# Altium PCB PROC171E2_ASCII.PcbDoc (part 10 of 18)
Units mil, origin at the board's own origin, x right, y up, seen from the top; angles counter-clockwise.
Board outline 7700 x 2300 mil, 6 copper layers (Top Layer, GND 1, SIG 1, SIG 2, GND 2, Bottom Layer), stack 61.062 mil thick; 938 components, 688 nets, 11933 pads, 1723 vias.
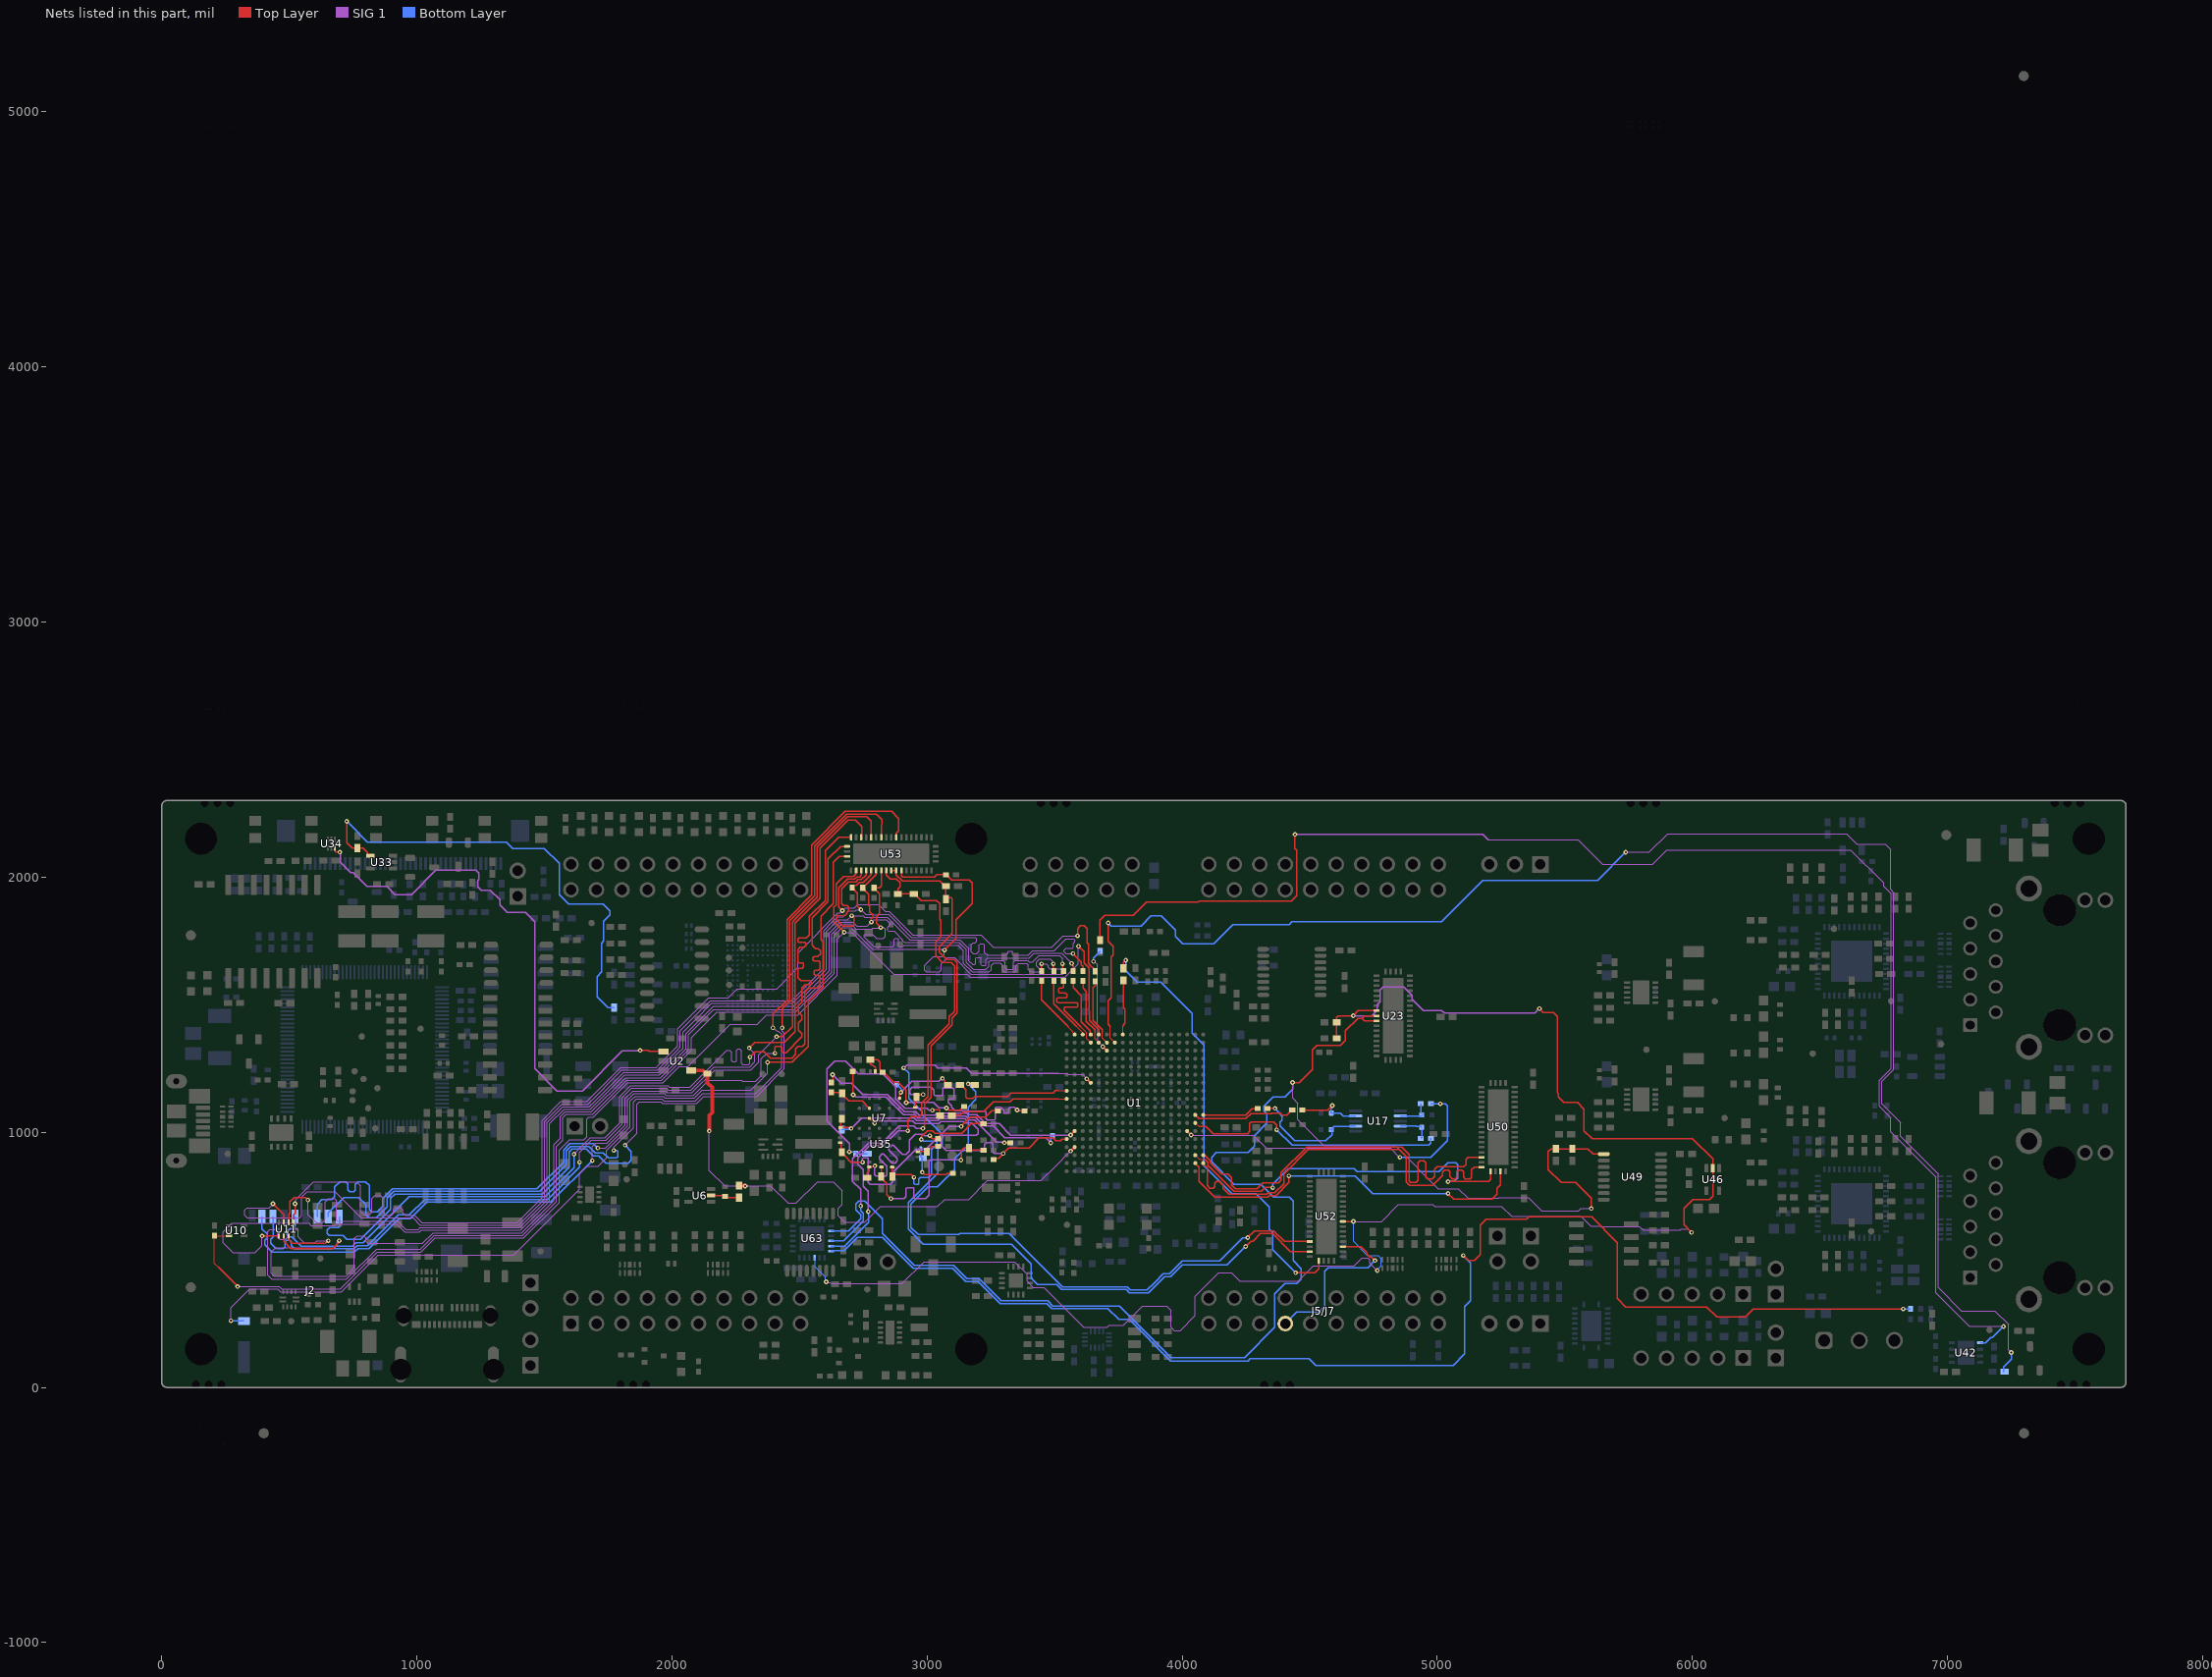
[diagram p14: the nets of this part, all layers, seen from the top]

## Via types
v1: diameter 18, hole 8, Top Layer to Bottom Layer, tented both sides, 1592 vias
v2: diameter 19.68, hole 7.87, Top Layer to Bottom Layer, tented both sides, 104 vias
v3: diameter 19.68, hole 7.87, Top Layer to Bottom Layer, 24 vias
v4: diameter 18, hole 8, Top Layer to Bottom Layer, 3 vias

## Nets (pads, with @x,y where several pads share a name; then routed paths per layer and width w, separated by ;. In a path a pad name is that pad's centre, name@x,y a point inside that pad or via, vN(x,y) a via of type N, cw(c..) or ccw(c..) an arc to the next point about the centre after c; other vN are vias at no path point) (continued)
AM263P_LIN2_TXD: R166.1 U52.39 | length 1782.1
  Top Layer w5.3: R166.1@3769.66,1642.44 3769.66,1665.2 v1(3778.82,1674.36) ; v1(4444.77,448.84) 4445.11,448.5 4519.71,448.5 4535.47,464.27 U52.39@4535.47,496.77
  Bottom Layer w5.3: v1(3778.82,1674.36) 3778.85,1661.78 3778.85,1657.39 3776.22,1654.76 3773,1651.53 3773,1638 3817.25,1593.75 3822.43,1588.57 3916.48,1588.57 3918.04,1587.02 4040,1465.06 4040,1388.66 4085.85,1342.81 4085.85,868.87 4195.74,758.98 4290,758.98 4341.87,707.11 4341.87,621.43 4354.64,608.66 4354.64,538.97 v1(4444.77,448.84)
AM263P_LIN2_TXD_PR0_PRU0_GPIO9: J5/J7.44 U52.3 | length 686.2
  Top Layer w5.3: U52.3@4629.96,551.89 4700.67,551.89 4724.05,528.5 4724.05,521.53 4735.14,510.45 4742.25,510.45 v1(4755.76,496.94)
  Bottom Layer w5.3: J5/J7.44@4404.17,250 4449.17,295 4535.31,295 4558.86,318.54 4558.86,454.51 4572.72,468.37 4727.19,468.37 v1(4755.76,496.94)
AM263P_LIN2_TXD_R: R166.2 U1.A8 | length 218.4
  Top Layer w4: U1.A8@3767.61,1382.8 3767.61,1414.29
  Top Layer w5.3: 3767.61,1414.29 3767.61,1418.04 3775.9,1426.33 3775.9,1481.99 3769.66,1488.22 R166.2@3769.66,1595.2
AM263P_MCAN3_RX: R249.1 U1.B7 | length 6218.3
  Top Layer w4: 3718.3,1414.47 3718.54,1414.23 3718.54,1369.1 U1.B7@3736.16,1351.48
  Top Layer w5.3: v1(3710,1820.18) 3710.05,1820.13 3710.05,1748.76 3729.52,1729.29 3729.52,1724.38 3729.57,1724.32 3729.57,1693.81 3721.77,1686.01 3721.77,1569.08 3721.56,1568.87 3721.56,1527.25 3710.06,1515.75 3710.06,1422.71 3718.3,1414.47
  SIG 1 w4.75: v1(5738.52,2097.5) 5831.21,2097.5 5903.56,2169.85 6604.05,2169.85 6643.91,2129.99 6756.07,2129.99 6777.03,2109.04 6777.03,1951.63 6789.52,1939.14 6789.52,1335.16 6789.52,1246.1 6743.49,1200.06 6743.49,1110.67 6815.53,1038.63 6815.53,984.47 6964.3,835.7 6964.3,390.66 7054.96,300 7185.73,300 7238.93,246.79 7238.93,147.52 v1(7250,136.46)
  Bottom Layer w5.3: v1(3710,1820.18) 3710.6,1820.18 3722.29,1808.49 3838.74,1808.49 3877.8,1847.55 3918.43,1847.55 3974.4,1791.58 3974.4,1766.76 4002.88,1738.28 4123.15,1738.28 4199.21,1814.33 4419.42,1814.33 4430.26,1825.18 5015.92,1825.18 5177.59,1986.84 5627.87,1986.84 v1(5738.52,2097.5) ; R249.1@7219.69,61.46 7219.69,79.68 7250,110 v1(7250,136.46)
AM263P_MCAN3_TX: R401.1 U42.1 | length 5733.5
  Top Layer w5.3: R401.1@3678.01,1749.69 R401.1@3679.98,1751.65 ; R401.1@3678.01,1753.62 3678.01,1830.11 3697.42,1849.52 3807.81,1849.52 3859.79,1901.5 4063.15,1901.5 4067.23,1905.58 4427.03,1905.58 4448.86,1927.4 4448.86,2105.88 4442.21,2112.53 v1(4442.21,2167.19)
  SIG 1 w4.75: 5200,2146.14 5552.02,2146.14 5647.16,2051 5844,2051 5899.97,2106.97 6620.38,2106.97 6750,1977.35 6750,1964.45 6779.47,1934.98 6779.47,1330.99 6779.47,1250.26 6733.44,1204.22 6733.44,1101.56 6777.03,1057.97 6777.03,1001.63 6954.25,824.41 6954.25,370.75 7086.18,238.82 v1(7219.69,238.82)
  SIG 1 w5.3: v1(4442.21,2167.19) 5178.95,2167.19 5200,2146.14
  Bottom Layer w5.3: U42.1@7127.91,174.84 7148.62,174.84 7169.59,195.81 7176.68,195.81 v1(7219.69,238.82)
AM263P_MCAN5_RX: U1.G4 U52.37 | length 3350.7
  Top Layer w5.3: v1(4248.9,552.05) 4249.56,552.05 4270.75,573.23 4277.33,573.23 4307.29,603.19 4353.85,603.19 4424.84,532.2 U52.37@4500.04,532.2
  Top Layer w10: v1(3625.87,1209.57) U1.G4@3641.62,1193.82
  SIG 1 w4: 3515.64,1230.74 3548.57,1230.74 3553.24,1226.06 3609.38,1226.06 v1(3625.87,1209.57)
  SIG 1 w5.3: v1(2908.1,1252.01) v1@2911.51,1252.01 ; v1@2911.51,1253.55 2920.61,1262.64 3031.75,1262.64 3042.39,1252.01 3153.29,1252.01 3174.56,1230.74 3515.64,1230.74
  Bottom Layer w5.3: v1(2908.1,1252.01) 2928.54,1231.57 2928.54,1133.26 2981.03,1080.77 2981.03,1069.89 3059.43,991.49 3059.43,950.66 3042.1,933.34 3042.1,839.53 2926.28,723.72 2926.28,636.68 2926.34,636.62 2926.34,620.07 2984.95,561.47 3330.22,561.47 3408.32,483.36 3408.32,427.64 3433.18,402.78 3507.09,402.78 3526.79,383.08 3780.43,383.08 3792.52,370.98 3867.44,370.98 3930.93,434.47 3954.71,434.47 4000.11,479.86 4174.91,479.86 4247.09,552.05 v1(4248.9,552.05)
AM263P_MCAN5_TX: R393.1 U52.35 | length 2509.6
  Top Layer w5.3: v1(3161.4,1189.84) R393.1@3187.04,1189.84 ; v1(4257.03,587.12) 4283.7,613.79 4358.24,613.79 4400.46,571.57 U52.35@4500.04,571.57
  Bottom Layer w5.3: v1(3161.4,1189.84) 3161.51,1189.84 3191.13,1160.22 3191.13,1127.96 3161.94,1098.76 3161.94,949.51 3108.72,896.29 3108.72,854.23 3041.29,786.8 3004.36,786.8 2936.88,719.32 2936.88,641.07 2936.94,641.01 2936.94,626.69 2964.58,599.05 2991.85,599.05 2992.14,598.77 3125.4,598.77 3129.26,602.64 3322.22,602.64 3531.18,393.68 3784.82,393.68 3796.91,381.58 3862.98,381.58 3893.03,411.63 3893.1,411.63 3926.54,445.07 3950.32,445.07 4001,495.75 4146.65,495.75 4237.43,586.52 4256.43,586.52 v1(4257.03,587.12)
AM263P_MCAN_STB: R248.2 U63.12 | length 5352.3
  Top Layer w5.3: v1(5101.72,516.99) 5121.65,497.06 5145.27,497.06 5168.3,520.09 5168.3,636.5 5181.69,649.89 5182.53,649.89 5191.73,659.09 5350.16,659.09 5359.07,668 5604.62,668 5705.96,566.66 5705.96,348.37 5739.06,315.27 6056.52,315.27 6096.31,275.48 6207.26,275.48 6239.03,307.24 v1(6826.84,307.24)
  Bottom Layer w5.3: U63.12@2623.77,534.26 2624.48,534.97 2639.07,534.97 2639.16,535.06 2674.13,535.06 2727.29,588.23 2824.14,588.23 2945.89,466.48 3100.81,466.48 3152.4,414.89 3199.9,414.89 3286.21,328.58 3468.82,328.58 3488.75,308.65 3708.84,308.65 3751.67,265.83 3792.01,265.83 3954.71,103.13 4257.79,103.13 4266.49,111.82 4497.18,111.82 4523.75,85.25 5060.87,85.25 5061.63,86.01 5062.07,86.01 5106.93,130.86 5106.93,313.17 5107.42,313.67 5107.42,316.96 5130.3,339.84 5130.3,488.41 v1(5101.72,516.99) ; v1@6826.26,307.24 v1(6826.84,307.24) R248.2@6855,307.24
AM263P_MDIO0_MDC: R61.1 R63.1 U17.9 | length 126.5
  Bottom Layer w5.3: U17.9@4855.28,1024.06 4856.52,1025.31 4916.69,1025.31 4919.5,1022.5 4935.6,1022.5 R63.1@4939.04,1019.06 ; R61.1@4935.59,975.79 4940,980.2 R63.1@4940,1013.63
AM263P_MDIO0_MDC_R: R61.2 U1.M17 | length 1050.8
  Top Layer w4: U1.M17@4051.07,1036.34 4065.59,1021.81
  Top Layer w5.3: 4065.59,1021.81 4093.28,1021.81 4114.06,1001.03 4121.4,993.69 4255.66,993.69 4265.03,1003.07 4265.03,1035.03 4270.92,1040.92 4357.99,1040.92 4370.7,1028.21 v1(4370.7,1009.53)
  Bottom Layer w5.3: v1(4370.7,1009.53) 4431.44,948.79 4966.19,948.79 4975,957.6 4975,975.75 R61.2@4974.96,975.79
AM263P_MDIO0_MDIO: R62.1 R64.1 U17.7 | length 132.8
  Bottom Layer w5.3: U17.7@4855.28,1063.43 R64.1@4941.22,1063.43 ; R62.1@4935.59,1111.7 4935.59,1075.62 4941.21,1070 R64.1@4944,1070
AM263P_MDIO0_MDIO_R: R62.2 U1.N16 | length 1294.4
  Top Layer w10: U1.N16@4019.57,1004.84 v1(4035.32,989.09)
  SIG 1 w4: v1(4035.32,989.09) 4114.06,989.09
  SIG 1 w4.75: 4114.06,989.09 4278.7,989.09 4330.25,937.54 4815.65,937.54 4851.26,901.93 v1(4853.62,901.93)
  Bottom Layer w5.3: v1(4853.62,901.93) 4974.46,901.93 5040,967.46 5040,1103 5031.39,1111.61 v1(5011.92,1111.61) 5011.82,1111.7 R62.2@4974.96,1111.7
AM263P_MMC0_CD: R40.1 U1.A5 U10.3 U53.2 | length 5276.1
  Top Layer w4.75: 222.39,469.98 206.73,485.63 R40.1@206.73,594.53 U10.3@263.65,594.53
  Top Layer w5.3: 222.39,469.98 v1(297.36,395) ; v1(2675.17,1783.7) 2675.17,1785.34 2635.14,1825.37 2635.14,1882.38 2643.93,1891.16 2643.93,1972.58 2673.77,2002.43 2711.32,2002.43 2720.37,2011.48 2720.37,2024.45 U53.2@2721.99,2026.07 ; v1(3593.34,1728.9) 3615,1707.24 3615,1664.03 3630.89,1648.14 3630.89,1648.08 3635.54,1643.43 3635.54,1515.34 3635.55,1515.28 3636.55,1438.26 3673.12,1401.69 U1.A5@3673.12,1382.8
  SIG 1 w4.75: v1(297.36,395) 298.07,395.71 366.87,395.71 458.05,395.71 458.6,395.16 459.06,395.16 469.24,384.98 699.94,384.98 844.54,529.57 1015.53,529.57 1071.84,585.89 1418.95,585.89 1557.84,724.79 1557.84,929.75 1599.1,971 1654.47,971 1666.71,983.24 1666.71,1051.71 1674,1059 1692,1059 1826.76,1193.76 1964.09,1193.76 1990.85,1220.53 2027.73,1257.4 2062.18,1257.4 2228.28,1423.5 2334.78,1423.5 2371.71,1460.43 2494.1,1460.43 2648.8,1615.13 2648.8,1757.33 v1(2675.17,1783.7) 2704.67,1783.7 2868.35,1620.03 2869.74,1618.63 3158.35,1618.63 3169.18,1607.81 3540.26,1607.81 3592.78,1660.33 3592.78,1693.97 3593.34,1694.52 v1(3593.34,1728.9)
AM263P_MMC0_CD_MUX: J2.9 U53.41 | length 3773.6
  Top Layer w5.3: v1(2374.56,1274.02) 2470.81,1274.02 2533.98,1337.18 2533.98,1376.45 2533.98,1511.43 2592.56,1570.01 2592.56,1747.03 2583.63,1755.96 2583.63,1833.15 2583.63,1845.86 2633.33,1895.55 2633.33,2058.59 2655.93,2081.19 U53.41@2686.56,2081.19
  SIG 1 w4.75: v1(271.44,261.02) 271.44,312.62 344.21,385.39 453.96,385.39 454.23,385.11 454.89,385.11 465.35,374.65 704.22,374.65 848.81,519.25 942.15,519.25 942.21,519.19 1379.33,519.19 1637.5,777.36 1637.5,837.94 1665.63,866.06 1709.86,866.06 1743.85,900.05 1743.85,928.21 1836.74,1021.11 1836.74,1122.46 1855.31,1141.04 1965.77,1141.04 1972.5,1134.31 2087.91,1134.31 2118.97,1165.38 2309.98,1165.38 2374.56,1229.95 v1(2374.56,1274.02)
  Bottom Layer w5.3: v1(271.44,261.02) 272.3,260.16 J2.9@321.97,260.16
AM263P_MMC0_CLK: R33.2 U11.1 U53.3 | length 4813.5
  Top Layer w5.3: U11.1@517.72,646.57 517.72,676.24 522.76,681.27 v1(522.76,719.45) ; v1(2668.36,1868.31) 2654.53,1882.15 2654.53,1957.78 2688.57,1991.83 2715.71,1991.83 2725.05,2001.17 2735.53,2001.17 2741.68,2007.32 U53.3@2741.68,2026.07 ; v1(3590,1770) 3590,1799.21 3600.13,1809.34 3615.78,1809.34 3627.54,1797.58 3627.54,1742.08 3632.71,1736.91 3632.71,1661.32 3641.49,1652.53 3652.35,1641.68 3652.35,1638.24 R33.2@3659.54,1631.05
  SIG 1 w4.75: v1(522.76,719.45) 524.7,721.39 524.7,735.57 595.21,806.09 764.45,806.09 780,790.54 780,689.1 791.64,677.46 815.94,677.46 823.99,685.51 823.99,739.81 835.39,751.21 858.79,751.21 871.44,738.56 871.44,680.97 878.15,674.26 900,674.26 907.66,681.93 907.66,698.12 915,705.46 935.75,705.46 945,696.21 945,684.26 955,674.26 991.71,674.26 1019.78,646.19 1393.97,646.19 1490.63,742.85 1490.63,1046.3 1564.66,1120.32 1665.63,1120.32 1799.37,1254.06 1939.11,1254.06 1941.89,1256.84 cw(c2276.21,957.37) 1961.39,1277.28 1995.86,1311.2 2022.85,1338.19 2022.85,1406.06 2142.92,1526.14 2219.72,1526.14 2256.12,1562.54 2410.68,1562.54 2494.16,1646.02 2494.16,1701.51 2570.79,1778.14 2572.18,1779.53 2572.18,1782.04 2649.82,1859.67 2659.9,1859.67 2668.36,1868.13 v1(2668.36,1868.31) ; v1@2668.45,1868.22 2678.73,1878.5 2715.55,1878.5 2728.65,1891.6 2808.88,1891.6 2810.79,1889.69 2835.79,1864.7 2851.85,1864.7 2941.55,1775 2942.94,1773.61 3211.39,1773.61 3260.01,1724.99 3488.2,1724.99 3533.21,1770 v1(3590,1770)
AM263P_MMC0_CLK_MUX: J2.5 U53.39 | length 3759.8
  Top Layer w5.3: v1(2305.75,1294.59) 2326.61,1315.45 2360.73,1315.45 2385.77,1290.42 2470.46,1290.42 2485.1,1305.05 2485.1,1326.89 2494.5,1336.29 2510.53,1336.29 2520.65,1346.41 2520.65,1550.44 2535.68,1565.47 2573.03,1565.47 2581.43,1573.87 2581.43,1609.25 2574.89,1615.78 2560.89,1615.78 2557.78,1618.89 2557.78,1632.28 2560.89,1635.38 2575.45,1635.38 2581.43,1641.35 2581.43,1665.96 2576.68,1670.71 2558.11,1670.71 2552.12,1676.7 2552.12,1682.82 2557.99,1688.69 2571.83,1688.69 2581.96,1698.82 2581.96,1711.43 2573.23,1720.16 2563.14,1720.16 2551.7,1731.59 2551.7,1732.67 2549.32,1735.06 2549.32,1833.15 2549.32,1841.52 2612.13,1904.34 2612.13,2071.87 2660.82,2120.56 U53.39@2686.56,2120.56
  SIG 1 w4.75: v1(1615.98,914.12) 1615.98,914.45 1679.34,977.81 1680.12,977.81 1680.33,978.02 1736.73,978.02 1795,1036.29 1795,1140.68 1837.75,1183.44 1983.34,1183.44 1990.06,1176.71 2070.35,1176.71 2214.27,1320.63 2227.09,1320.63 2234.25,1313.48 2234.25,1280.57 2238.3,1276.53 2248.73,1276.53 2252.53,1280.32 2252.53,1320.14 2258.78,1326.4 2265.47,1326.4 2271.96,1319.91 2271.96,1270.43 2276.34,1266.06 2300.9,1266.06 2305.75,1270.91 v1(2305.75,1294.59)
  Bottom Layer w5.3: J2.5@522.76,669.61 522.76,634.79 509.41,621.44 502.92,621.44 491.43,609.95 491.43,599.14 501.08,589.49 510.38,589.49 546.06,553.81 748.96,553.81 760.91,565.76 788.8,565.76 970.06,747.02 1502.58,747.02 1615.98,860.43 v1(1615.98,914.12)
AM263P_MMC0_CLK_R: R33.1 U1.B6 | length 266.1
  Top Layer w4: 3687.64,1387.89 3687.64,1368.27 U1.B6@3704.61,1351.3
  Top Layer w5.3: R33.1@3659.54,1591.68 3659.54,1575.93 3650.97,1567.36 3650.97,1438.83 3687.64,1402.16 3687.64,1387.89
AM263P_MMC0_CMD: R34.2 U11.2 U53.4 | length 4889.6
  Top Layer w5.3: U11.2@498.04,646.57 498.04,678.5 503.23,683.69 503.23,727.54 519.46,743.77 563.58,743.77 v1(573.09,734.25) ; v1(2704.82,1848.92) 2713.5,1840.23 2713.5,1810.27 2710.4,1807.17 2670.78,1807.17 2645.74,1832.21 2645.74,1846.82 2648.1,1849.18 2648.84,1849.92 2653.24,1849.92 2666.79,1848.77 ccw(c2668.45,1868.22) 2684.52,1857.13 2692.59,1868.82 2692.59,1882.16 2685.54,1889.22 2672.73,1889.22 2665.13,1896.82 2665.13,1953.39 2692.96,1981.23 2720.1,1981.23 2729.44,1990.57 2743.02,1990.57 2761.36,2008.91 U53.4@2761.36,2026.07 ; v1(3566.83,1661.6) 3566.83,1658.16 3573,1651.99 R34.2@3573,1632.17
  SIG 1 w4.75: v1(573.09,734.25) 573.09,677.22 605.31,645 628.72,645 640,656.28 640,727.32 652.68,740 676.6,740 685,731.6 685,655 689.31,650.69 925.2,650.69 957.03,618.86 1005.9,618.86 1013.13,626.09 1055.19,626.09 1402.3,626.09 1510.73,734.53 1510.73,1037.97 1572.98,1100.22 1676.37,1100.22 1810.11,1233.96 1947.43,1233.96 1959.49,1246.02 2029.06,1315.59 2042.95,1329.48 2042.95,1392.59 2093.4,1443.05 2155.67,1505.31 2473.31,1505.31 2606,1638 2606,1787.43 2626.92,1808.35 2651.87,1833.3 2689.19,1833.3 v1(2704.82,1848.92) 2749.92,1848.92 2754.33,1844.51 2755.72,1843.12 2782.57,1843.12 2782.64,1843.05 2845.07,1843.05 2846.98,1841.15 2933.23,1754.9 2934.62,1753.51 3129.7,1753.51 3163.48,1719.74 3163.48,1671.72 3178.14,1657.05 3186.14,1657.05 3191.15,1662.07 3191.15,1682.48 3193.93,1685.26 3209.52,1685.26 3212.3,1682.48 3212.3,1656.28 3215.08,1653.5 3228.41,1653.5 3231.19,1656.28 3231.19,1677.22 3237.62,1683.64 3400.47,1683.64 3418.77,1701.95 3526.48,1701.95 v1(3566.83,1661.6)
AM263P_MMC0_CMD_MUX: J2.3 U53.38 | length 3757.6
  Top Layer w5.3: v1(2403.69,1309.94) 2403.69,1333.19 2406.8,1336.29 2426.66,1336.29 2429.76,1333.19 2429.76,1317.74 2435.64,1311.86 2446.9,1311.86 2510.05,1375.01 2510.05,1385.95 2496.52,1399.48 2496.52,1429.36 2510.05,1442.89 2510.05,1458.33 2496.52,1471.86 2496.52,1497.11 2509.57,1510.17 2509.57,1564.57 2522.98,1577.98 2542.9,1577.98 2546,1581.08 2546,1591.98 2542.83,1595.14 2504.59,1595.14 2493.16,1606.58 2493.16,1638.81 2496.86,1642.52 2510.66,1642.52 2515.43,1647.29 2515.43,1660.98 2512.63,1663.77 2496.94,1663.77 2493.16,1667.56 2493.16,1716.21 2501.29,1724.35 2517.73,1724.35 2523.98,1730.6 2523.98,1740.19 2520.64,1743.53 2497.9,1743.53 2493.16,1748.27 2493.16,1758.05 2497.77,1762.66 2527.28,1762.66 2538.72,1774.1 2538.72,1833.15 2538.72,1845.91 2601.53,1908.73 2601.53,2103.35 2654.17,2156 U53.38@2702.31,2156
  SIG 1 w4.75: v1(1709.17,938.04) 1739.4,938.04 1826.05,1024.7 1826.05,1025.41 1826.14,1025.5 1826.14,1126.85 1850.92,1151.64 1970.16,1151.64 1976.89,1144.91 2083.52,1144.91 2143.03,1204.42 2273.09,1204.42 2277.03,1200.48 2329.29,1200.48 2349.67,1220.86 2349.67,1287.4 2372.22,1309.94 v1(2403.69,1309.94)
  Bottom Layer w5.3: J2.3@609.37,669.61 609.37,717.57 628,736.2 666.72,736.2 677.39,746.87 677.39,785.59 697.9,806.09 720.7,806.09 728.57,798.22 728.57,773.79 736.24,766.13 751.5,766.13 758.91,773.54 758.91,796.04 768.97,806.09 799.28,806.09 813.89,791.48 813.89,697.22 822.5,688.61 845.2,688.61 865.47,708.88 865.47,739.37 904.92,778.82 1470.84,778.82 1575.26,883.24 1575.26,930.99 1599.11,954.84 1646.86,954.84 1692.37,954.84 v1(1709.17,938.04)
AM263P_MMC0_CMD_R: R34.1 U1.A4 | length 238.4
  Top Layer w5.3: R34.1@3573,1592.8 3573,1567.42 3605,1535.42 3605,1433.11 3639.62,1398.48 3639.62,1384.79 U1.A4@3641.62,1382.8
AM263P_MMC0_D0: R35.2 R386.1 U11.3 U53.5 | length 5111.3
  Top Layer w5.3: v1(436.14,719.45) 478.35,677.24 U11.3@478.35,646.57 ; v1(2740.42,1872.35) 2740.42,1872.63 2726.86,1886.19 2726.86,1937.51 2706.97,1957.4 2706.97,1961.33 2714.16,1968.53 2722.61,1968.53 2734.05,1979.97 2750.52,1979.97 2781.05,2010.5 U53.5@2781.05,2026.07 ; v1(3571.76,1700) 3604.4,1667.36 3604.4,1659.64 ; 3604.43,1659.62 3604.43,1656.55 3611,1649.98 R35.2@3611,1632.17
  SIG 1 w4.75: v1(436.14,719.45) 420.83,704.14 334.14,704.14 325,695 325,675 335,665 539.81,665 549.08,674.26 549.08,745.74 569.32,765.98 680,765.98 781.77,664.21 984.38,664.21 1012.44,636.14 1398.14,636.14 1500.68,738.69 1500.68,1042.13 1568.82,1110.27 1669.79,1110.27 1803.53,1244.01 1943.27,1244.01 1951.6,1252.34 2017.91,1318.76 2032.9,1333.75 2032.9,1396.23 2032.9,1398.2 2035.68,1400.98 2088.46,1453.1 2151.51,1515.36 2468.36,1515.36 2595,1642 2595,1790.64 2626.92,1822.56 2647.71,1843.35 2651.41,1844.04 2671.32,1844.04 2683.53,1856.25 2691,1865.66 2693.78,1868.45 2719.71,1868.45 2723.62,1872.35 v1(2740.42,1872.35) ; v1@2740.56,1872.49 2759.88,1853.17 2786.73,1853.17 2786.8,1853.1 2806.41,1853.1 2806.56,1853.26 2849.08,1853.26 2937.39,1764.95 2938.78,1763.56 3188.99,1763.56 3193.88,1758.67 3193.88,1748 3188.96,1743.08 3180.09,1743.08 3173.53,1736.52 3173.53,1708.22 3181.71,1700.04 3194.5,1700.04 3204.48,1710.02 3204.48,1734.45 3209.44,1739.41 3222.09,1739.41 3225.68,1735.81 3225.68,1704.29 3236.28,1693.69 3308.07,1693.69 3316.97,1702.59 3316.97,1707.55 3319.75,1710.34 3332.9,1710.34 3335.68,1707.55 3335.68,1696.48 3338.46,1693.69 3396.31,1693.69 3414.61,1712 3497.75,1712 3544.42,1758.67 3574.11,1758.67 3579.33,1753.45 3579.33,1745.49 3574.09,1740.25 3574.09,1724.22 3571.3,1721.44 3544.9,1721.44 3537.18,1713.71 3537.18,1707 3544.18,1700 v1(3571.76,1700)
AM263P_MMC0_D0_MUX: J2.7 U53.36 | length 3757.7
  Top Layer w5.3: v1(2302.92,1330.48) 2324.88,1352.44 2440.17,1352.44 2464.18,1376.45 2482.56,1394.83 2482.56,1819.74 2495.97,1833.15 2580.33,1917.51 2580.33,2113.16 2690.78,2223.61 2718.42,2223.61 2744,2198.03 U53.36@2744,2156
  SIG 1 w4.75: v1(1638.2,882.48) 1638.2,921.68 1684.49,967.97 1740.9,967.97 1805.05,1032.12 1805.05,1135.74 1842.14,1172.84 1978.95,1172.84 1985.67,1166.11 2074.74,1166.11 2164.08,1255.46 2304.51,1255.46 2325.28,1276.22 2325.28,1307.19 2302.92,1329.55 v1(2302.92,1330.48)
  Bottom Layer w5.3: J2.7@436.14,669.61 436.14,589.22 427.31,580.39 427.31,564.71 448.8,543.21 475.59,543.21 482.69,550.32 482.69,569.23 489.55,576.09 501.35,576.09 507.69,569.75 507.69,555.14 519.62,543.21 753.35,543.21 765.3,555.16 806.7,555.16 927.5,675.96 970.21,675.96 1030.67,736.42 1512.41,736.42 1638.2,862.21 v1(1638.2,882.48)
AM263P_MMC0_D0_R: R35.1 U1.B5 | length 267.2
  Top Layer w4: 3657.37,1390.67 3657.37,1367.05 U1.B5@3673.12,1351.3
  Top Layer w5.3: R35.1@3611,1592.8 3611,1566 3624.4,1552.6 3624.4,1435.42 3657.37,1402.45 3657.37,1390.67
AM263P_MMC0_D1: R36.2 R385.1 U11.6 U53.6 | length 5006.3
  Top Layer w5.3: v1(393.42,593.25) 393.59,593.43 U11.6@458.67,593.43 ; v1(2781.35,1823.85) 2781.35,1836.36 2787.97,1842.98 2787.97,1851.54 2775.25,1864.27 2775.25,1887.05 2771.05,1891.25 2771.05,1933.14 2748.06,1956.14 2748.06,1960.07 2755.25,1967.27 2757.22,1967.27 2800.73,2010.78 U53.6@2800.73,2026.07 ; v1(3530.86,1660.05) 3530.86,1636.3 R36.2@3535,1632.17
  SIG 1 w4.75: v1(393.42,593.25) 393.42,554.93 366.39,527.91 278.68,527.91 240,566.59 240,610 274.25,644.25 576.46,644.25 585.85,634.85 587.24,633.46 676.72,633.46 683.9,640.64 921.04,640.64 952.86,608.81 1010.06,608.81 1017.29,616.04 1059.36,616.04 1406.46,616.04 1520.78,730.36 1520.78,1033.81 1577.14,1090.17 1680.53,1090.17 1814.27,1223.91 1951.6,1223.91 1967.2,1239.52 2033.22,1305.54 2055.08,1327.39 2055.08,1386.7 2163.18,1494.81 2478.81,1494.81 2617,1633 2617,1781.18 2658.87,1823.05 2661.16,1823.05 2661.36,1823.25 2709.1,1823.25 2725.09,1807.26 2764.76,1807.26 v1(2781.35,1823.85) 2790.51,1833 2840.91,1833 2856.22,1817.69 2856.22,1813.76 2846.37,1803.91 2846.37,1790.5 2849.15,1787.72 2870.73,1787.72 2904.17,1754.27 2904.17,1750.06 2910.77,1743.46 3125.54,1743.46 3153.43,1715.57 3153.43,1666.19 3180.41,1639.21 3229.93,1639.21 3241.53,1650.81 3241.53,1667.52 3247.6,1673.59 3298.34,1673.59 3305.82,1666.12 3305.82,1644.5 3311.58,1638.74 3335.38,1638.74 3338.72,1642.07 3338.72,1666.7 3344.57,1672.56 3395.28,1672.56 3401.22,1666.61 3413.95,1666.61 3439.23,1691.9 3519.54,1691.9 3530.86,1680.58 v1(3530.86,1660.05)
AM263P_MMC0_D1_MUX: J2.8 U53.34 | length 3758.5
  Top Layer w5.3: v1(2410.24,1374.64) 2432.79,1374.64 2471.96,1413.81 2471.96,1824.13 2480.98,1833.15 2569.73,1921.9 2569.73,2117.55 2688.33,2236.15 2764.22,2236.15 2781.05,2219.32 U53.34@2781.05,2156
  SIG 1 w4.75: v1(1688.2,888.4) 1688.2,944.69 1701.41,957.9 1743.55,957.9 1745.06,957.92 1816,1028.86 1816,1131.7 1846.53,1162.24 1974.55,1162.24 1981.28,1155.51 2079.13,1155.51 2168.47,1244.86 2308.91,1244.86 2339.07,1275.02 2339.07,1303.48 v1(2410.24,1374.64)
  Bottom Layer w5.3: J2.8@392.83,669.61 392.83,621.44 412.94,601.34 412.94,585.16 405.02,577.25 405.02,558.26 433.52,529.76 755.15,529.76 758.26,532.87 758.26,533.13 769.69,544.56 812.22,544.56 928.51,660.86 973.54,660.86 1038.51,725.82 1524.13,725.82 1686.7,888.4 v1(1688.2,888.4)
AM263P_MMC0_D1_R: R36.1 U1.B4 | length 490
  Top Layer w4: 3601.58,1414.29 3625.87,1390 3625.87,1367.05 U1.B4@3641.62,1351.3
  Top Layer w5.3: R36.1@3535,1592.8 3535.16,1592.64 3535.16,1580.99 3535.12,1580.94 3535.12,1568.69 3532.01,1565.58 3517.93,1565.58 3514.83,1562.48 3514.83,1549.97 3517.93,1546.87 3540.93,1546.87 3547.57,1540.23 3547.57,1530.56 3544.46,1527.46 3511.96,1527.46 3508.85,1524.35 3508.85,1512.26 3513.35,1507.77 3587.55,1507.77 3590.65,1504.66 3590.65,1494.1 3586.1,1489.55 3541.65,1489.55 3536.18,1484.08 3536.18,1479.69 3552.93,1462.95 3601.58,1414.29
AM263P_MMC0_D2: R37.2 R384.1 U11.7 U53.7 | length 5525.9
  Top Layer w5.3: U11.7@478.35,593.43 478.35,571.65 505.48,544.52 669.3,544.52 695.98,571.21 v1(695.98,574.65) ; R384.1@2792.16,1958.1 2812.53,1958.1 2820.42,1966 U53.7@2820.42,2026.07 ; R384.1@2792.16,1960.07 2792.16,1956.14 2813.04,1935.25 2813.04,1918.25 2814.17,1917.12 2814.17,1874.86 2814.3,1874.73 2814.3,1864.27 2814.22,1864.19 2814.22,1858.31 2800.88,1844.96 2800.88,1819.59 v1(2818.2,1802.27) ; v1(3494.86,1660.24) 3494.86,1634.3 R37.2@3497,1632.17
  SIG 1 w4.75: v1(695.98,574.65) 687.35,566.01 687.35,557.12 676.74,546.51 446.51,546.51 430.11,530.11 430.11,447.99 441.64,436.46 723,436.46 755,468.46 755,583.25 765,593.25 791.75,593.25 800,585 800,572.73 808.85,563.88 1021.4,563.88 1063.52,605.99 1410.63,605.99 1537.74,733.11 1537.74,951.54 1561.89,975.68 1561.89,1060.7 1581.31,1080.12 1684.69,1080.12 1818.44,1213.86 1955.76,1213.86 2037.37,1295.47 ; 2037.39,1295.49 2065.13,1323.23 2065.13,1382.54 2163.11,1480.53 2479.94,1480.53 2626.92,1627.52 2626.92,1628.71 2627.05,1628.84 2627.05,1777.01 2663.03,1813 2705.14,1813 2720.93,1797.21 2783.76,1797.21 2786.33,1799.78 2815.71,1799.78 v1(2818.2,1802.27) 2829.92,1802.27 2836.32,1795.87 2836.32,1768.02 2828.2,1759.9 2802.74,1759.9 2786.85,1775.79 2755.75,1775.79 2752.97,1773 2752.97,1765.17 2791.39,1726.74 2864.95,1726.74 2871.68,1733.47 2871.68,1755.76 2875.82,1759.9 2884.34,1759.9 2888.8,1755.44 2888.8,1729.53 2891.58,1726.74 2904.55,1726.74 2911.21,1733.41 3121.38,1733.41 3143.38,1711.41 3143.38,1662.03 3176.25,1629.16 3243.42,1629.16 3251.58,1637.32 3251.58,1653.74 3261.38,1663.54 3287.1,1663.54 3295.77,1654.88 3295.77,1634.13 3301.21,1628.69 3342.08,1628.69 3348.77,1635.38 3348.77,1654.22 3357.06,1662.51 3391.11,1662.51 3397.12,1656.5 3397.12,1637.97 3406.4,1628.69 3443.82,1628.69 3446.6,1631.47 3446.6,1635.4 3429.75,1652.26 3429.75,1668.2 3441.03,1679.48 3483.07,1679.48 3492.33,1670.22 3492.33,1662.78 v1(3494.86,1660.24)
AM263P_MMC0_D2_MUX: J2.1 U53.32 | length 3757
  Top Layer w5.3: v1(2431.8,1409.49) 2431.8,1484.2 2461.36,1513.76 2461.36,1828.52 2465.98,1833.15 2559.13,1926.29 2559.13,2121.94 2683.94,2246.75 2801.9,2246.75 2823.78,2224.87 2823.78,2206.08 2820.42,2202.72 U53.32@2820.42,2156
  SIG 1 w4.75: v1(1816.37,949.19) 1862.83,995.64 1862.83,1110.01 1872.66,1119.84 1956.99,1119.84 1963.72,1113.11 2096.69,1113.11 2124.66,1141.08 2332.34,1141.08 2440.36,1249.1 2440.36,1387.98 2431.8,1396.55 v1(2431.8,1409.49)
  Bottom Layer w5.3: J2.1@695.98,669.61 695.98,629.46 692.88,626.36 657.54,626.36 648.36,617.19 648.36,604.08 656.39,596.06 709.19,596.06 725.21,580.04 779.9,580.04 897.49,697.63 897.49,741.41 913.7,757.62 1491.33,757.62 1596.46,862.75 1596.46,922.21 1607.89,933.64 1665.49,933.64 1691.21,907.92 1712.5,907.92 1741.9,878.52 1828.28,878.52 1840.53,890.77 1840.53,925.02 v1(1816.37,949.19)
AM263P_MMC0_D2_R: R37.1 U1.A3 | length 257.6
  Top Layer w4: 3584.29,1415.65 3610.12,1389.82 U1.A3@3610.13,1382.8
  Top Layer w5.3: R37.1@3497,1592.8 3496.11,1591.91 3496.11,1572.59 3496.07,1572.55 3496.07,1503.87 3584.29,1415.65
AM263P_MMC0_D3: R38.2 R383.1 U11.8 U53.11 | length 5767.7
  Top Layer w5.3: U11.8@498.04,593.43 498.04,577.3 509.79,565.55 640.14,565.55 649.24,574.65 v1(652.68,574.65) ; U53.11@2899.16,2026.07 2899.16,2004.24 2903.17,2000.23 3028.68,2000.23 3037.72,2009.27 3076.02,2009.27 3095.92,1989.38 3165.37,1989.38 3177.32,1977.42 3177.32,1897.18 3113.15,1833.01 3113.15,1759.04 v1(3068.27,1714.16) ; R38.2@3449,1632.17 v1(3449,1660.23)
  SIG 1 w4.75: v1(652.68,574.65) 651.96,573.93 607.59,573.93 599.42,565.76 558.64,565.76 535,589.4 535,614.59 524.59,625 504.26,625 495.34,616.08 495.34,589.74 485,579.4 463.85,579.4 455,588.25 455,608.19 444.33,618.86 423.61,618.86 415.82,611.07 415.82,439.18 431.52,423.48 724.23,423.48 842.26,541.51 1013.25,541.51 1067.68,595.94 1414.79,595.94 1547.79,728.95 1547.79,944.32 1571.94,968.46 1571.94,1056.54 1585.47,1070.07 1688.86,1070.07 1822.6,1203.81 1959.92,1203.81 2077.07,1320.96 2077.07,1370.6 2176.96,1470.48 2484.1,1470.48 2626.92,1613.3 2637,1623.38 2637,1624.57 2637.1,1624.67 2637.1,1772.85 2667.2,1802.95 2700.98,1802.95 2787.23,1716.69 3065.74,1716.69 v1(3068.27,1714.16) 3068.27,1696.45 3059.46,1687.63 3024.43,1687.63 2990.9,1654.1 2990.9,1635.38 2997.59,1628.68 3047.94,1628.68 3056.58,1637.32 3056.58,1660.34 3080.45,1684.22 3106.98,1684.22 3171.17,1620.03 3172.56,1618.64 3373.49,1618.64 ccw(c3377.87,1637.38) 3382.25,1618.64 3530.25,1618.64 3533.03,1621.42 3533.03,1637.2 3530.25,1639.99 3481.5,1639.99 3475.46,1646.02 3475.46,1652.8 3468.03,1660.23 v1(3449,1660.23)
AM263P_MMC0_D3_MUX: J2.2 U53.29 | length 3758.9
  Top Layer w5.3: v1@2395.8,1409.72 2395.8,1463.19 2450.76,1518.15 2450.76,1832.91 2450.99,1833.15 2548.53,1930.68 2548.53,2126.33 2679.55,2257.35 2861.18,2257.35 2888.64,2229.89 2888.64,2181.62 2879.47,2172.45 U53.29@2879.47,2156
  SIG 1 w4.75: v1(1772.09,928.85) 1773.12,929.88 1773.12,941.12 1848.96,1016.96 1848.96,1118.34 1861.05,1130.44 1961.38,1130.44 1968.11,1123.71 2092.3,1123.71 2120.27,1151.68 2327.95,1151.68 2429.76,1253.49 2429.76,1383.59 2417.77,1395.59 2412.71,1395.59 v1(2395.8,1409.49)
  Bottom Layer w5.3: J2.2@652.68,669.61 652.68,683.39 713.82,744.52 772.3,744.52 800.52,716.3 800.52,676.5 812.81,664.21 841.67,664.21 883.75,706.3 883.75,742.67 909.31,768.22 1481.68,768.22 1585.86,872.4 1585.86,926.6 1603.5,944.24 1657.7,944.24 1674.39,944.24 1700.11,918.52 1730.94,918.52 1750.31,899.15 1782.62,899.15 1787.66,904.18 1787.66,924.1 1783.74,928.01 1772.92,928.01 v1(1772.09,928.85)
AM263P_MMC0_D3_R: R38.1 U1.A2 | length 263.7
  Top Layer w4: 3552.24,1414.29 3552.24,1414.13 3572.18,1394.19 3572.18,1390.31 3578.63,1383.86 U1.A2@3578.63,1382.8
  Top Layer w5.3: R38.1@3449,1592.8 3449,1519.25 3552.24,1416.01 3552.24,1414.29
AM263P_MMC0_WP: R41.1 U1.C6 | length 424.5
  Top Layer w10: v1(3688.87,1335.55) U1.C6@3704.61,1319.8
  SIG 1 w4: 3669.62,1414.29 3669.62,1354.8 v1(3688.87,1335.55)
  SIG 1 w4.75: v1(3652.26,1669.37) 3655.1,1669.37 3667.42,1657.05 3667.42,1416.49 3669.62,1414.29
  Bottom Layer w5.3: v1(3652.26,1669.37) 3652.26,1682.6 3678.01,1708.35 R41.1@3678.01,1710.32
AM263P_MMC_MUX_EN: R390.2 R392.2 U53.8 U63.11 | length 2051.5
  Top Layer w5.3: U53.8@2840.1,2026.07 2840.1,2008.48 2855.49,1993.1 2879.58,1993.1 2893.92,1978.76 2893.92,1961.82 2886.08,1953.99 R392.2@2886.08,1934.22 2947.25,1934.22 R390.2@2947.83,1933.65 2951.77,1933.65 2976.89,1908.52 3036.96,1908.52 3049.74,1895.75 3049.74,1834.27 3054.23,1829.78 3054.23,1820.75 3054.34,1820.64 3054.34,1767.74 3033.75,1747.15 3033.75,1692.02 3060.58,1665.2 3093.94,1665.2 3107.13,1652.01 3107.13,1472.83 3087.38,1453.09 3087.38,1425.36 3004.15,1342.13 3004.15,1139.87 2979.16,1114.88 2979.16,1069.61 2970.94,1061.39 2939.09,1061.39 2924.43,1046.73 v1(2924.43,1005.77)
  SIG 1 w5.3: v1(2769.54,688.99) 2769.54,768.12 2749.16,788.49 2749.16,853.7 2739.9,862.96 2739.66,862.96 2728.23,874.4 2728.23,900.05 2775.18,947 2828.2,947 2887.1,1005.9 2924.3,1005.9 v1(2924.43,1005.77)
  Bottom Layer w5.3: U63.11@2623.77,553.95 2677.36,553.95 2770.18,646.77 2770.18,688.35 v1(2769.54,688.99)
AM263P_MMC_MUX_SEL: R389.2 R391.2 U53.9 U53.10 U63.10 | length 2082.9
  Top Layer w5.3: U53.9@2859.79,2026.07 U53.10@2879.47,2026.07 2879.47,2008.94 2903.02,1985.39 3049.22,1985.39 3069.78,1964.83 R391.2@3073.72,1964.83 ; v1(2983.42,1015.2) 2983.42,1017.54 2990.53,1024.65 2990.53,1111.26 3014.75,1135.48 3014.75,1337.74 3098.23,1421.21 3098.23,1448.45 3117.73,1467.95 3117.73,1664.7 3105.51,1676.92 3077.9,1676.92 3048.75,1706.07 3048.75,1727.83 3099.07,1778.16 3099.07,1916.02 3095.97,1919.12 R389.2@3077.57,1919.12 ; R391.2@3072.15,1962.75 3073.18,1961.72 R389.2@3073.18,1927.45
  SIG 1 w5.3: v1(2740.08,711.06) 2740.08,776.18 2708.26,807.99 2708.26,895.08 2770.79,957.6 2822.39,957.6 2890.08,1025.29 2948.1,1025.29 2958.47,1014.92 2983.14,1014.92 v1(2983.42,1015.2)
  Bottom Layer w5.3: U63.10@2623.77,573.63 2672.14,573.63 2750.16,651.65 2750.16,681.31 2740.08,691.4 v1(2740.08,711.06)
AM263P_OSPI0_CLK: R26.1 R438.2 U7.B2 | length 177.2
  Top Layer w5.3: R26.1@2624.76,1156.11 2663.8,1156.11 R438.2@2667.19,1152.72 2667.19,1148.78 2693.41,1122.56 2745.28,1122.56 U7.B2@2773.92,1093.92
AM263P_OSPI0_CLK_R: R26.2 U1.N2 | length 1089.6
  Top Layer w5.3: R26.2@2629.76,1195.48 v1(2629.76,1225.55) ; v1(3562.88,989.09) U1.N2@3578.63,1004.84
  SIG 1 w5.3: v1@2630.72,1226.06 2630.72,1224.6 2662.88,1192.44 2704.03,1192.44 2748.52,1147.96 2843.63,1147.96 2911,1080.59 2954.65,1080.59 2968.38,1066.86 3031.64,1066.86 3039,1074.22 3156.82,1074.22 3161.73,1069.31 3194.88,1069.31 3229.61,1034.58 3282,1034.58 3327.49,989.09 3491,989.09 v1(3562.88,989.09)
AM263P_OSPI0_CSN0: R31.2 U1.P1 U7.C2 | length 1292.4
  Top Layer w5.3: U7.C2@2773.92,1054.55 2774.79,1054.55 2793.81,1035.53 v1(2794.69,1035.53) ; R31.2@3261.19,894.73 3264.65,898.18 3281.31,898.18 3298.22,915.09 v1(3298.22,917.02) 3319.86,938.67 3399.68,938.67 3439.14,978.13 3492.97,978.13 3503.32,967.77 3523.21,967.77 3528.79,973.35 U1.P1@3547.13,973.35
  SIG 1 w5.3: v1(2794.69,1035.53) 2795.22,1035.53 2804.14,1044.45 2943.93,1044.45 2953.32,1035.06 3046.71,1035.06 3054.07,1042.42 3141.75,1042.42 3147.72,1036.45 3174.75,1036.45 3199.61,1011.59 3199.61,994.84 3191.96,987.2 3067.47,987.2 3053.07,972.8 3053.07,949.34 3074.17,928.24 3216.62,928.24 3226,937.62 3226,951.58 3234.42,960 3251.47,960 3257.49,953.98 3257.49,922.78 3263.25,917.02 v1(3298.22,917.02)
AM263P_OSPI0_D0: R27.1 R42.1 R374.2 R377.1 | length 764.1
  Top Layer w5.3: R27.1@2820.72,863.34 2820.72,826.33 2829.26,817.79 2829.26,811.69 2842.05,798.9 2842.05,754.95 2857,740 v1(2858.68,740) ; v1(3132.76,890.89) 3134.63,892.76 3134.63,928.7 3144.34,938.42 R42.1@3164.53,938.42 3173.35,929.6 R377.1@3221.22,929.6
  SIG 1 w5.3: v1(2858.68,740) 2910.31,740 2917.97,747.66 2917.97,779.88 2921.08,782.98 2945.65,782.98 2948.76,779.88 2948.76,743.1 2951.86,740 2994.21,740 3007.22,753.01 3007.22,885.74 3013.38,891.9 3131.76,891.9 v1(3132.76,890.89)
AM263P_OSPI0_D1: R28.1 R43.1 R373.2 R378.1 | length 797.1
  Top Layer w5.3: R373.2@2666.41,1052.94 2660.72,1047.25 R28.1@2660.72,1018.36 2695.22,1018.36 2698.93,1014.65 v1(2702.36,1014.65) ; v1(3303,958.84) R378.1@3326.79,958.84
  SIG 1 w5.3: v1(2702.36,1014.65) 2704.26,1014.65 2744.66,1055.05 2950.21,1055.05 2959.6,1045.66 3042.32,1045.66 3049.68,1053.02 3148.04,1053.02 3154.01,1047.05 3186.94,1047.05 3273.25,960.74 3301.11,960.74 v1(3303,958.84)
  Bottom Layer w5.3: R43.1@2665.66,1010.62 2666.09,1011.05 v1@2695.33,1011.05
AM263P_OSPI0_D2: R29.1 R372.1 R379.1 | length 879.3
  Top Layer w5.3: R29.1@2954.22,1097.9 2954.22,1125.35 2957.95,1129.08 R372.1@2959.2,1129.08 ; R372.1@2960.67,1129.08 R372.1@2959.2,1129.08 ; v1(2984.63,1147.96) 2968.36,1147.96 2963.02,1142.62 2963.02,1134.14 2959.2,1137.96 R372.1@2959.2,1129.08 ; v1(3353.38,1086.92) 3356.82,1086.92 3360.12,1083.62 R379.1@3382.25,1083.62
  SIG 1 w5.3: v1(2984.63,1147.96) 2937.14,1147.96 2931.77,1153.32 2931.77,1166.47 2941.89,1176.58 3015.3,1176.58 3026.7,1165.18 3026.7,1147.38 3029.81,1144.28 3058.22,1144.28 3061.32,1147.38 3061.32,1170.19 3064.43,1173.3 3100.99,1173.3 3105.02,1169.26 3105.02,1135.36 3101.08,1131.42 3086.21,1131.42 3082.62,1127.83 3082.62,1116.19 3095.69,1103.13 3095.69,1098 3108.87,1084.82 3161.21,1084.82 3163.88,1082.15 3226.9,1082.15 3230,1079.05 3230,1054.42 3236.17,1048.25 3264.65,1048.25 3267.76,1051.35 3267.76,1094.27 3270.86,1097.37 3288.43,1097.37 3301.21,1084.6 3301.21,1076.89 3304.32,1073.79 3316.64,1073.79 3319.75,1076.89 3319.75,1092.63 3324.49,1097.37 3342.93,1097.37 v1(3353.38,1086.92)
AM263P_OSPI0_D3: R30.1 R371.2 R380.1 | length 221.5
  Top Layer w5.3: v1(2981.2,843.58) 2990.08,834.7 3074.1,834.7 3078.11,838.71 R380.1@3101.46,838.71
  Bottom Layer w5.3: R30.1@2975.51,935.56 2975.51,905.73 R371.2@2983.07,898.17 2981.2,896.29 v1(2981.2,843.58)
AM263P_OSPI0_D4: R361.1 R370.2 R403.1 | length 89.8
  Top Layer w5.3: R361.1@2964.2,923.76 R370.2@2999.42,923.81 R370.2@2999.42,923.81 2999.42,927.74 3008.58,936.9 3012.51,936.9 3020.23,944.62 R403.1@3043.1,944.62
AM263P_OSPI0_D5: R167.1 R365.1 R369.2 | length 735.9
  Top Layer w5.3: R365.1@2863.91,863.34 R369.2@2863.91,826.33 2871.59,834.01 2937.49,834.01 v1(2948.27,823.24) ; v1(2977.41,972.03) 2979.45,974.08 2979.45,983.62 3001.97,1006.14 3021.4,1006.14 3029.74,997.8 3030.02,997.8 3031.15,996.66 3136.03,996.66 3173.45,1034.08 R167.1@3221.22,1034.08
  Bottom Layer w5.3: v1(2948.27,823.24) 2948.27,798.48 2951.37,795.37 2964.58,795.37 2967.69,798.48 2967.69,817.19 2973.73,823.24 3007.61,823.24 3017.67,833.3 3017.67,931.66 3038.14,952.13 3038.14,961.5 3035.04,964.6 2986.86,964.6 2979.43,972.03 v1(2977.41,972.03)
AM263P_OSPI0_D6: R366.1 R368.2 R404.1 | length 667.5
  Top Layer w5.3: R368.2@2765.43,822.18 2765.43,839.99 2773.92,848.48 R366.1@2773.92,863.34 2775.29,864.72 2788.2,864.72 2792.02,868.53 v1(2795.45,868.53) ; v1(3010.32,986.62) 3022.06,974.88 R404.1@3043.1,974.88
  SIG 1 w5.3: v1@2794.46,865.65 2794.46,833.8 2799.43,828.84 2838.51,828.84 2841.61,831.94 2841.61,867.45 2812.63,896.43 2812.63,904.21 2822.61,914.19 2828.18,914.19 2863.41,878.95 2874.12,878.95 2882.88,887.72 2882.88,897.58 2849.29,931.18 2849.29,935.57 2863.28,949.56 2867.67,949.56 2903.57,913.66 2917.61,913.66 2930.12,926.16 2930.12,968.01 2953.66,991.56 2985.63,991.56 2990.57,986.62 v1(3010.32,986.62)
AM263P_OSPI0_D7: R168.1 R367.2 R376.1 | length 927.6
  Top Layer w5.3: R376.1@2659.78,959.13 2659.87,959.13 2662.73,956.27 2662.73,925.79 R367.2@2666.59,921.93 2666.59,917.99 2675.75,908.83 2676.67,908.83 2702.29,883.22 2747.02,883.22 v1(2747.75,882.48) ; v1(3133.67,1022.9) 3133.67,1023.45 3170.03,1059.81 3229.72,1059.81 3254.24,1084.33 3277.08,1084.33 R168.1@3277.81,1083.59
  SIG 1 w5.3: v1(2747.75,882.48) 2746.51,883.73 2746.51,896.95 2749.61,900.05 2766.73,900.05 2769.84,896.95 2769.84,802.48 2776.93,795.39 2855.33,795.39 2865.77,805.82 2865.77,840.96 2958.22,933.41 2995.51,933.41 3085.73,1023.63 3132.93,1023.63 v1(3133.67,1022.9)
AM263P_OSPI0_DQS: R375.1 R381.1 R402.1 R437.2 | length 558.8
  Top Layer w5.3: R381.1@2797.2,1238.43 2797.2,1253.12 2787.04,1263.29 2782.37,1263.29 2777.21,1268.46 R437.2@2777.21,1284.43 2805.27,1284.43 2814.65,1275.05 2814.65,1245.5 2824.12,1236.03 2828.06,1236.03 2866.96,1197.13 2866.96,1195.96 2886.62,1195.96 2918.08,1164.49 v1(2918.08,1116.11) ; v1(3076.16,1095.04) 3078.33,1095.04 3086.57,1086.8 3128.88,1086.8 3142.99,1100.9 R402.1@3144.95,1100.9
  SIG 1 w5.3: v1(2918.08,1116.11) 3024.45,1116.11 3045.52,1095.04 v1(3076.16,1095.04)
AM263P_OSPI0_LBCLK: R165.1 R382.1 | length 978.6
  Top Layer w5.3: R382.1@2710.23,1236.43 2710.23,1211.14 2710.41,1210.95 v1(2710.41,1147.09)
  SIG 1 w5.3: v1(2710.41,1147.09) 2720.15,1137.36 2839.24,1137.36 2907.78,1068.82 2951.43,1068.82 2963.99,1056.26 3036.03,1056.26 3043.39,1063.62 3152.43,1063.62 3158.4,1057.65 3191.33,1057.65 3225,1023.98 3259.43,1023.98 3304.92,978.49 3464.99,978.49 v1(3485,958.48)
  Bottom Layer w5.3: v1@3485,957.89 3485,978.64 R165.1@3491.78,985.43
AM263P_OSPI0_RST: R99.1 R387.1 U35.1 | length 1016.5
  Top Layer w5.3: v1(3020.85,1086.39) 3023.11,1088.64 3047.32,1088.64 3050.42,1085.53 R99.1@3050.42,1064.94
  SIG 1 w5.3: v1(2695.27,923.31) 2695.27,956.09 2606.85,1044.52 2606.85,1247.2 2639.18,1279.52 2679.63,1279.52 2730.56,1228.6 2827.4,1228.6 2876.75,1179.25 2876.75,1129.83 2912.64,1093.94 3000.01,1093.94 3007.53,1086.43 3020.81,1086.43 v1(3020.85,1086.39)
  Bottom Layer w5.3: v1(2695.27,923.31) 2710.97,923.31 R387.1@2713.76,920.52 ; R387.1@2719.86,923.31 2727.22,915.95 U35.1@2764.38,915.95
AM263P_OSPI0_RST_R: R99.2 U1.J1 | length 479
  Top Layer w4: 3515.64,1130.83 U1.J1@3547.13,1130.83
  Top Layer w5.3: R99.2@3095.05,1066.26 3129.63,1066.26 3138.27,1074.9 ; 3138.04,1075.13 3143.92,1081.01 3220.94,1081.01 3259.67,1119.74 3325.32,1119.74 3336.41,1130.83 3515.64,1130.83
AM263P_OSPI_ECS: R13.1 R435.1 U7.A5 | length 284.5
  Top Layer w5.3: U7.A5@2892.03,1133.29 2892.03,1147.88 2897.67,1153.52 v1(2897.67,1156.85) ; v1(3060.2,1210.91) 3060.53,1210.91 3069.7,1201.74 3069.7,1194.53 3078.87,1185.36 R13.1@3081.53,1185.36
  SIG 1 w5.3: v1(2897.67,1156.85) 2940.5,1199.69 3045.88,1199.69 v1@3059.57,1213.38
  Bottom Layer w5.3: R435.1@2882.02,1186.8 2882.02,1185.62 2888.55,1179.09 2889.73,1179.09 2897.67,1171.16 v1(2897.67,1156.85)
AM263P_OSPI_ECS_R: R13.2 U1.H1 | length 469
  Top Layer w4: 3515.64,1162.32 U1.H1@3547.13,1162.32
  Top Layer w5.3: R13.2@3128.78,1185.36 3132.71,1185.36 3151.1,1166.97 3151.1,1138.91 3157.41,1132.6 3179.7,1132.6 3188.04,1140.94 3315.99,1140.94 3324.63,1149.58 3325.18,1149.58 3329.46,1153.87 3493.88,1153.87 3502.33,1162.32 3515.64,1162.32
AM263P_PORZ: R6.2 R19.1 U1.R2 U2.4 | length 2274.6
  Top Layer w10: v1(3562.88,926.1) U1.R2@3578.63,941.85
  Top Layer w15: U2.4@2075.37,1242.05 2122.24,1242.05 2135.16,1229.13 R6.2@2139.09,1229.13 2139.09,1193.43 2157.4,1175.12 2157.4,1076.8 2146.04,1065.44 v1(2146.04,1005) ; R19.1@2262.84,791.01 2266.35,791.01 2267.16,790.2 2285.24,790.2 2286.45,788.99 v1(2287.26,788.99)
  SIG 1 w4.75: v1(2146.04,1005) 2146.04,849.67 2206.72,788.99 v1(2287.26,788.99) 2288.47,790.2 2386.44,790.2 2454.61,722.03 2486.91,722.03 2571.13,806.25 2633.14,806.25 2667.94,771.44 2667.94,716.55 2652.25,700.86 2652.25,673.19 2677.63,647.81 2755.58,647.81 2816.93,709.16 3041.11,709.16 3068.94,736.99 3163.35,736.99 3237.21,810.85 3447.22,810.85 3503.75,867.38 3562.47,926.1 v1(3562.88,926.1)
AM263P_PORZ_PB: U2.1 U34.6 | length 2242.4
  Top Layer w5.3: U34.6@678.78,2115.47 679.48,2114.78 679.48,2102.52 683,2099 697,2099 v1(698,2098) ; v1(1875.01,1320.45) 1906.2,1320.45 1909.97,1316.68 1966.94,1316.68 U2.1@1967.11,1316.85
  SIG 1 w5.3: v1@700,2096 700,2058 740.43,2017.57 750.6,2017.57 804.51,1963.67 883.33,1963.67 915,1932 978.74,1932 1074.55,2027.82 1231.57,2027.82 1243.01,2016.38 1243.01,1991.05 1239.4,1987.44 1239.4,1962.11 1252.69,1948.82 1287.83,1948.82 1325.66,1911 1325.66,1891.33 1355.44,1861.54 1426.3,1861.54 1462.32,1825.53 1462.32,1249.63 1550.05,1161.9 1648.41,1161.9 1805.97,1319.46 1874.02,1319.46 v1(1875.01,1320.45)
AM263P_PORZ_RC: C63.2 R19.2 U6.2 | length 113.5
  Top Layer w5.3: U6.2@2152.96,752.39 2199.22,752.39 2207.84,743.77 R19.2@2262.84,743.77
AM263P_PR0_MDIO0_MDC: R71.1 R73.1 U17.2 | length 477
  Top Layer w5.3: R71.1@4335.03,1092.85 4344.19,1093.59 v1(4364.18,1093.59)
  Bottom Layer w5.3: v1(4364.18,1093.59) 4391.37,1062.76 4391.5,1054.85 cw(c4371.98,1054.54) 4391.5,1054.21 4391.37,1046.69 4387.83,1043.15 cw(c4371.98,1054.54) 4384.35,1039.44 4384.35,1023.49 4385.9,1021.94 4441.12,966.71 4563.02,966.71 4587,990.69 4587,1008.52 R73.1@4584.97,1010.55 ; R73.1@4578.57,1010.55 4584.48,1010.55 4591.67,1017.74 4591.67,1018.9 4594.77,1022 4655.59,1022 4657.65,1024.06 U17.2@4680.08,1024.06
AM263P_PR0_MDIO0_MDC_R: R71.2 U1.L18 | length 223.4
  Top Layer w5.3: U1.L18@4082.57,1067.84 4249.17,1067.84 4267.46,1086.12 ; 4267.49,1086.09 4274.26,1092.85 R71.2@4295.66,1092.85
AM263P_PR0_MDIO0_MDIO: R72.1 R74.1 U17.4 | length 258.6
  Top Layer w5.3: R72.1@4471.3,1086.73 4570.89,1086.73 v1(4588.41,1104.25)
  Bottom Layer w5.3: R74.1@4583,1074.9 4619.79,1074.9 4631.26,1063.43 U17.4@4680.08,1063.43 ; R74.1@4584.97,1074.9 4583,1076.87 4583,1095.4 4588.41,1100.82 v1(4588.41,1104.25)
AM263P_PR0_MDIO0_MDIO_R: R72.2 U1.L17 | length 407
  Top Layer w5.3: U1.L17@4051.07,1067.84 4065.59,1053.31 4114.06,1053.31 4249.7,1053.31 4269.35,1072.96 4351,1072.96 4352.11,1074.07 4384.9,1074.07 4392.06,1066.91 4410.73,1066.91 4422.17,1078.34 4422.17,1078.94 4429.96,1086.73 R72.2@4431.93,1086.73
AM263P_PRU/BP_MUX_EN: R288.2 R290.2 U23.8 U46.2 U52.8 U63.15 | length 7129
  Top Layer w5.3: R290.2@4605.35,1367.93 R288.2@4605.35,1430.9 4605.35,1449.54 4612.31,1456.5 v1(4670.59,1456.5) 4690.28,1476.18 U23.8@4762.24,1476.18 ; U52.8@4638.9,650.1 4639.12,650.32 v1(4671.61,650.32) ; v1(5400.67,1484.48) 5415.73,1469.42 5455.79,1469.42 5471.6,1453.61 5471.6,1154.42 5474.81,1151.21 5474.81,1137.32 5495.85,1116.28 5549.4,1116.28 5575.39,1090.3 5575.39,1006.33 5606.79,974.93 6000.49,974.93 6080,895.42 U46.2@6080,859.29 6080,749 6067.5,736.5 6001.5,736.5 5966.5,701.5 5966.5,637.37 v1(5996.69,607.19)
  SIG 1 w4.75: v1(2604.37,413.92) 2606.91,411.39 2619.92,411.39 2625.15,406.16 2902.78,406.16 2988.55,491.93 3342.83,491.93 3391.8,442.96 3391.8,416.66 3416.22,392.23 3458.95,392.23 3614.51,236.67 3706.16,236.67 3713.55,244.07 3770.29,244.07 3844.35,318.12 3939.08,318.12 3956.05,301.15 3956.05,236.07 3962.86,229.25 3968.89,223.22 3992.33,223.22 4051.04,281.93 4051.04,357.38 4119.85,426.19 4143.9,450.25 4192.88,450.25 4225.83,417.3 4455.4,417.3 4514.78,476.69 4673.43,476.69 4704.13,507.38 4728.04,507.38 4736.51,498.91 4736.51,486.23 v1(4764.83,457.91) ; v1(4671.61,650.32) 4782.02,650.32 4847.94,716.24 4982.38,716.24 4988.89,709.74 5252.04,709.74 5291.65,670.12 5563.49,670.12 5600.94,632.68 5640.51,632.68 5642.12,631.06 5792.46,631.06 5807.17,616.35 5951.31,616.35 5955.76,620.8 5983.07,620.8 v1(5996.69,607.19)
  SIG 1 w5.3: v1(4670.59,1456.5) 4742.56,1456.5 4765.57,1479.51 4765.57,1500.24 4776.33,1511 4776.33,1557.06 4788.26,1568.99 4867.86,1568.99 4900.78,1536.07 4900.78,1521.59 4944.59,1477.78 5017.45,1477.78 5027.93,1467.3 5381.88,1467.3 v1@5400.26,1485.68
  Bottom Layer w4.75: U63.15@2558.81,508.67 2560.95,506.52 2560.95,473.38 2601.91,432.42 2601.91,416.38 v1(2604.37,413.92) ; v1(4671.61,650.32) 4671.61,571.6 4726.63,516.58 4768.32,516.58 4779.15,505.76 4779.15,475.82 4764.83,461.5 v1(4764.83,457.91)
AM263P_PRU_MUX_SEL: R287.2 R289.2 U23.9 U23.10 U49.1 U63.8 | length 6284.1
  Top Layer w5.3: v1(4432.87,1194.81) 4459.49,1194.81 4511.32,1246.64 4511.32,1323.6 4528.38,1340.65 4620.51,1340.65 4640.24,1360.38 4640.24,1397.6 4689.41,1446.77 4704.17,1446.77 ; U23.10@4762.24,1436.81 4714.13,1436.81 4704.17,1446.77 ; U23.9@4762.24,1456.5 4713.9,1456.5 4704.17,1446.77 ; R289.2@5465.31,934.34 5466.14,935.17 R287.2@5530,935.17 5530.85,934.32 5591.07,934.32 5610.59,914.8 U49.1@5652.8,914.8 ; R289.2@5465.31,935.17 5445,935.17 5435,925.17 5435,853.97 5485.91,803.06 5541.94,803.06 5603.51,741.49 v1(5603.51,701.16)
  SIG 1 w4.75: v1(4432.87,1194.81) 4432.87,1133.78 4452.68,1113.97 4452.68,1048.98 4554.07,947.59 4835.18,947.59 5003.52,779.25 5082.63,779.25 5120.9,740.98 5239.67,740.98 5242.55,743.86 5357.75,743.86 5409.9,691.71 5553.22,691.71 5562.67,701.16 v1(5603.51,701.16)
  Bottom Layer w5.3: U63.8@2623.77,613 2691.82,613 2739.57,660.74 2739.57,676.92 2720.55,695.93 2720.55,719.15 2731.99,730.58 2755.56,730.58 2824.64,661.5 2824.64,602.72 2949.85,477.51 3104.78,477.51 3156.79,425.49 3204.29,425.49 3290.6,339.18 3473.21,339.18 3493.14,319.25 3753.58,319.25 3956.2,116.62 4244.2,116.62 4363.14,235.56 4363.14,367 4402.34,406.2 4449.17,406.2 4467.17,424.2 4467.17,465.63 4436.24,496.57 4436.24,717.46 4435.91,730.09 4420.55,745.45 4359.54,745.45 4308.88,796.1 4203.59,796.1 4115.57,884.12 4115.57,902.28 4133.42,920.12 4258.29,920.12 4283.46,945.29 4283.46,986.56 4332.45,1035.55 4332.45,1072.99 4320.31,1085.13 4320.31,1101.3 4357.55,1138.55 4402.38,1138.55 4432.87,1169.04 v1(4432.87,1194.81)
AM263P_RESETN_PB: R5.1 R179.1 U33.4 | length 1888.5
  Top Layer w5.3: v1(725.32,2218.82) 725.32,2135.29 746.84,2113.77 765.8,2113.77 R179.1@766.36,2114.33 ; R179.1@770,2113 789.3,2113 805.66,2096.64 805.66,2089.81 810.88,2084.59 U33.4@817.71,2084.59
  Bottom Layer w5.3: v1(725.32,2218.82) 807.15,2137 1351,2137 1375.88,2112.12 1499.65,2112.12 1558.18,2053.59 1558.18,1931.13 1595.21,1894.1 1730.58,1894.1 1757.17,1867.51 1757.17,1851.33 1745.74,1839.9 1745.58,1839.9 1732.8,1827.11 1732.8,1749.23 1725.06,1741.49 1725.06,1628.41 1706.75,1610.09 1706.75,1530.92 1749.48,1488.19 R5.1@1773.66,1488.19
AM263P_RGMII1_RD0: U1.U17 U50.41 | length 1460.3
  Top Layer w5.3: U1.U17@4051.07,878.86 4066.92,863.01 4066.92,807.86 4128.46,746.32 4335.88,746.32 4341.94,752.37 4367.52,752.37 4418.22,803.07 v1(4418.22,828.66) ; v1(5042.25,760) 5064.19,738.05 5214.98,738.05 5234.87,757.94 5234.87,780.48 5248.23,793.84 U50.41@5248.23,846.81
  Bottom Layer w5.3: v1(4418.22,828.66) 4678.37,828.66 4747.02,760 v1(5042.25,760)
AM263P_RGMII1_RD1: U1.T17 U50.39 | length 1458.8
  Top Layer w4: U1.T17@4051.07,910.35 4068.04,893.38 4088.58,893.38
  Top Layer w5.3: 4088.58,893.38 4100.07,881.9 4100.07,871.48 4114.06,857.49 4203.62,767.93 4310.43,767.93 4325.97,783.46 4354.08,783.46 v1(4355.04,782.5) ; v1(5042.25,806.62) 5200.48,806.62 5208.86,815 U50.39@5208.86,846.81
  Bottom Layer w5.3: v1(4355.04,782.5) 4355.04,795.46 4417.19,857.6 4674.33,857.6 4685.56,846.38 5007.17,846.38 5041.65,880.85 5071.86,880.85 5080,872.72 5080,821.62 5065,806.62 v1(5042.25,806.62)
AM263P_RGMII1_RD2: U1.U18 U50.38 | length 1577.5
  Top Layer w5.3: U1.U18@4082.57,878.86 4082.57,876.03 4086.94,871.66 4086.94,871.45 4098.22,860.18 4098.22,815.87 4098.22,791.55 4108.91,780.87 4122.22,780.87 4127.72,786.36 4127.72,800 4135.42,807.7 4145,807.7 4160,792.7 4160,780.71 4183.79,756.92 4331.49,756.92 4337.55,762.97 4363.13,762.97 4398.69,798.54 4398.69,836.74 4494,932.05 4851.59,932.05 4878.64,905 4878.64,805.54 4891.48,792.7 4981.47,792.7 5019.79,831.02 5019.79,843.75 5027.3,851.27 5043.73,851.27 5050,845 5050,826.48 5059.26,817.22 5070.4,817.22 5076.16,822.99 5076.16,845 5082.43,851.27 5096.48,851.27 5102.75,845 5102.75,824.02 5109.55,817.22 5128.99,817.22 5135,823.23 5135,852.56 5145,862.56 U50.38@5173.43,862.56
AM263P_RGMII1_RD3: U1.T18 U50.36 | length 1572
  Top Layer w5.3: U1.T18@4082.57,910.35 4084.56,908.36 4090.01,908.36 4109.5,888.87 4109.5,881.36 4114.06,876.8 4154.46,836.4 4180.44,836.4 4193.62,823.23 4193.62,792.92 4208.01,778.53 4293.29,778.53 4316.78,802.02 4377.63,802.02 4388.09,812.49 4388.09,841.13 4489.61,942.65 4860,942.65 4890,912.65 4890,809.17 4895.88,803.3 4916.09,803.3 4923.6,810.8 4923.6,879.87 4931.24,887.51 4947.13,887.51 4955,879.64 4955,825 4963.5,816.5 4980.44,816.5 4990,826.05 4990,855 4999.32,864.32 5098.42,864.32 5098.46,864.28 5103.12,864.28 5112.25,873.41 5112.25,894.17 5120,901.93 U50.36@5173.43,901.93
